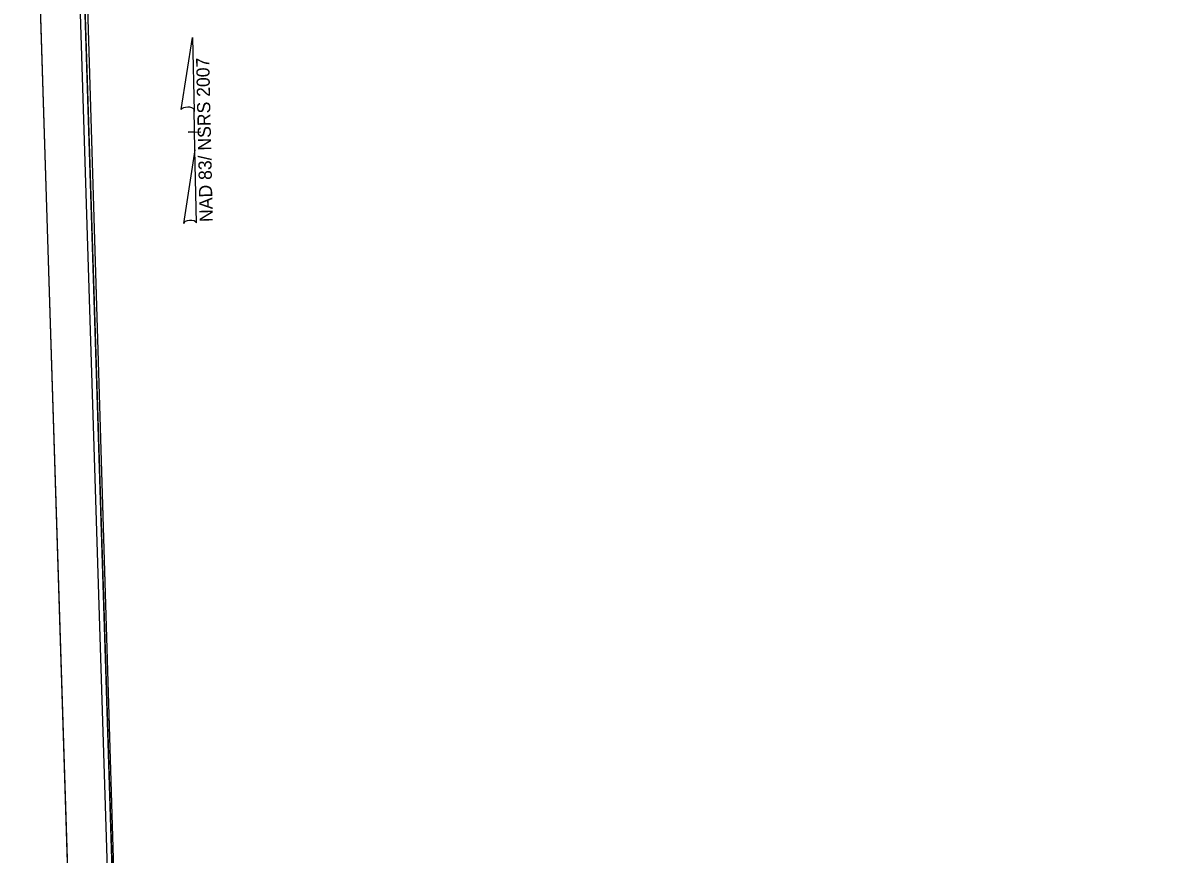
# Model space of a CAD drawing. Extents: x 2326025 to 2327173, y 123144 to 125024.
# Drawn here: x 2326025 to 2326599, y 124287 to 124705 of the extents above; entities that cross this region are included whole.
import ezdxf

# ---------------------------------------------------------------- set-up
doc = ezdxf.new("R2010")
doc.units = 0
for name, color, linetype in [('Prop North Arrow NAD83 for Plan Sheets CELL', 7, 'Continuous'), ('Sheet Clip Boundary CELL', 7, 'Continuous'), ('Sheet Cutting Line CELL', 7, 'Continuous'), ('Sheet Layout Plan Border', 7, 'Continuous'), ('Sheet Plan CELL', 7, 'Continuous'), ('Sheet Plan Layout CELL', 7, 'Continuous'), ('Sheet Plot Border Inside CELL', 7, 'Continuous'), ('Sheet Plot Border Outside CELL', 7, 'Continuous')]:
    doc.layers.add(name, color=color, linetype=linetype)

msp = doc.modelspace()

# ---------------------------------------------------------------- linework, layer by layer
at = {"layer": 'Prop North Arrow NAD83 for Plan Sheets CELL'}
for p, q in [((2326105.04, 124661.38), (2326110.62, 124697.56)), ((2326110.66, 124697.56), (2326110.62, 124697.56)), ((2326110.66, 124697.56), (2326110.62, 124697.56)), ((2326110.66, 124697.56), (2326111.48, 124660.39)), ((2326111.91, 124641.11), (2326111.46, 124661.48)), ((2326111.48, 124660.39), (2326111.46, 124661.44)), ((2326108.6, 124650.06), (2326108.56, 124650.06)), ((2326111.36, 124650.12), (2326108.6, 124650.06)), ((2326108.63, 124650.06), (2326114.86, 124650.2)), ((2326111.91, 124641.11), (2326106.22, 124604.22)), ((2326112.75, 124604.52), (2326111.91, 124641.11))]:
    msp.add_line(p, q, dxfattribs=at)
for centre, start_param, end_param in [((2326108.26, 124661.06), 0.216388, 2.908219), ((2326109.52, 124604.17), 0.201328, 3.141593)]:
    msp.add_ellipse(centre, major_axis=(3.29, 0.05), ratio=0.461098, start_param=start_param, end_param=end_param, dxfattribs=at)
at = {"layer": 'Sheet Clip Boundary CELL'}
msp.add_lwpolyline([(2327143.22, 123556.44), (2327101.01, 124955.82), (2326262.87, 124930.53), (2326268.58, 124741.36), (2326057.19, 124734.98), (2326093.7, 123524.78)], close=True, dxfattribs=at)
at = {"layer": 'Sheet Cutting Line CELL'}
msp.add_line((2326025.47, 124989.14), (2326078.49, 123306.48), dxfattribs=at)
at = {"layer": 'Sheet Layout Plan Border'}
msp.add_lwpolyline([(2327143.22, 123556.44), (2327101.01, 124955.82), (2326262.87, 124930.53), (2326268.58, 124741.36), (2326057.19, 124734.98), (2326093.7, 123524.78)], close=True, dxfattribs=at)
at = {"layer": 'Sheet Plan CELL'}
for points in [[(2326048.48, 124972.88), (2326095.72, 123473.59), (2327145.2, 123506.66), (2327097.96, 125005.93)], [(2327145.2, 123506.66), (2326095.75, 123473.57), (2326054.77, 124772.91), (2326204.76, 124777.65), (2326198.47, 124977.58), (2327097.96, 125005.93)]]:
    msp.add_lwpolyline(points, close=True, dxfattribs=at)
at = {"layer": 'Sheet Plan Layout CELL'}
msp.add_lwpolyline([(2326095.24, 123474.78), (2327144.73, 123506.47), (2327099.5, 125005.78), (2326261.37, 124980.5), (2326268.58, 124741.36), (2326057.19, 124734.98)], close=True, dxfattribs=at)
at = {"layer": 'Sheet Plot Border Inside CELL'}
msp.add_lwpolyline([(2327152.55, 123353.33), (2327100.07, 125018.49), (2326045.6, 124985.27), (2326098.07, 123320.1)], close=True, dxfattribs=at)
at = {"layer": 'Sheet Plot Border Outside CELL'}
msp.add_lwpolyline([(2327172.95, 123340.96), (2327119.93, 125023.63), (2326025.47, 124989.14), (2326078.49, 123306.48)], close=True, dxfattribs=at)

# ---------------------------------------------------------------- texts
at = {"layer": 'Prop North Arrow NAD83 for Plan Sheets CELL'}
msp.add_text('NAD 83/ NSRS 2007', height=6.6111, rotation=91.26352, dxfattribs=at).set_placement((2326120.89, 124604.97))

doc.saveas('drawing.dxf')
